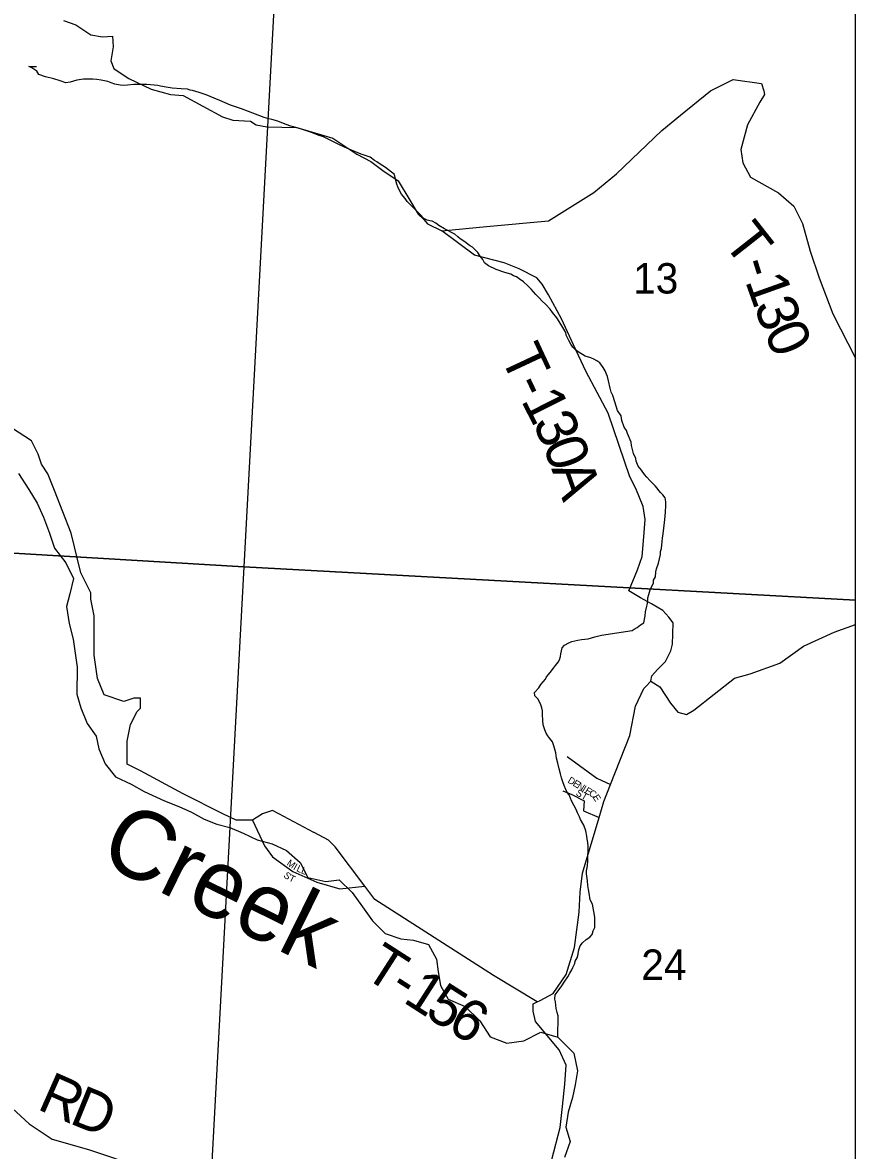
# Model space of a CAD drawing. Extents: x 1949938.81 to 1949945.61, y 152207.65 to 152214.09.
# Drawn here: x 1949944.46 to 1949945.607, y 152211.223 to 152212.776 of the extents above; entities that cross this region are included whole.
import ezdxf

# ---------------------------------------------------------------- set-up
doc = ezdxf.new("R2010")
doc.units = 0
for name, color, linetype in [('GM_X_County', 7, 'Continuous'), ('GM_X_County_Road', 7, 'Continuous'), ('GM_X_County_Road_Text', 7, 'Continuous'), ('GM_X_Minor_River', 7, 'Continuous'), ('GM_X_Minor_River_Text', 7, 'Continuous'), ('GM_X_Section', 7, 'Continuous'), ('GM_X_Section_Text', 7, 'Continuous'), ('GM_X_Township', 7, 'Continuous'), ('GM_X_Township_Road', 7, 'Continuous'), ('GM_X_Township_Road_Text', 7, 'Continuous'), ('GM_X_Township_ROW', 7, 'Continuous'), ('GM_X_Township_Subdivision', 7, 'Continuous'), ('GM_X_Township_Subdivision_Text', 7, 'Continuous')]:
    doc.layers.add(name, color=color, linetype=linetype)

msp = doc.modelspace()

# ---------------------------------------------------------------- linework, layer by layer
at = {"layer": 'GM_X_County'}
msp.add_lwpolyline([(1949945.6069, 152208.8266), (1949945.6069, 152214.0874), (1949938.8069, 152214.0874), (1949938.8069, 152213.1813)], dxfattribs=at)
at = {"layer": 'GM_X_County_Road'}
for points in [[(1949945.3182, 152211.8618), (1949945.3182, 152211.8618), (1949945.3252, 152211.8688), (1949945.3375, 152211.861), (1949945.352, 152211.8389), (1949945.3624, 152211.8264), (1949945.3742, 152211.823), (1949945.3845, 152211.8292), (1949945.4404, 152211.8733), (1949945.462, 152211.8791), (1949945.5029, 152211.8936), (1949945.5355, 152211.9172), (1949945.5775, 152211.9366), (1949945.6069, 152211.9469)], [(1949943.7253, 152211.8724), (1949943.7713, 152211.8759), (1949943.7925, 152211.8688), (1949943.8248, 152211.8553), (1949943.8598, 152211.8405), (1949943.959, 152211.7945), (1949944.0299, 152211.7626), (1949944.0547, 152211.7307), (1949944.0901, 152211.674), (1949944.1184, 152211.6421), (1949944.2424, 152211.5252), (1949944.2637, 152211.5004), (1949944.3132, 152211.426), (1949944.3876, 152211.3339), (1949944.4691, 152211.2594), (1949944.501, 152211.2382), (1949944.5506, 152211.224), (1949944.6249, 152211.1992)], [(1949945.189, 152211.2101), (1949945.2003, 152211.2539), (1949945.2036, 152211.2831), (1949945.2068, 152211.314), (1949945.2084, 152211.3399), (1949945.1987, 152211.361), (1949945.1662, 152211.4), (1949945.163, 152211.4146), (1949945.163, 152211.4243), (1949945.1686, 152211.4271), (1949945.1727, 152211.4292), (1949945.1906, 152211.4389), (1949945.2084, 152211.4649), (1949945.2198, 152211.5022), (1949945.2263, 152211.5508), (1949945.2279, 152211.5784), (1949945.2311, 152211.6044), (1949945.2538, 152211.6811), (1949945.2603, 152211.7033), (1949945.2694, 152211.7265), (1949945.296, 152211.7942), (1949945.3041, 152211.8347), (1949945.3155, 152211.859), (1949945.3182, 152211.8618)]]:
    msp.add_lwpolyline(points, dxfattribs=at)
at = {"layer": 'GM_X_Minor_River'}
for points in [[(1949945.0903, 152212.4545), (1949945.087, 152212.4595), (1949945.0833, 152212.463), (1949945.0795, 152212.4668), (1949945.0754, 152212.4692), (1949945.0691, 152212.4742), (1949945.0627, 152212.4785), (1949945.0593, 152212.4812), (1949945.0552, 152212.4847), (1949945.041, 152212.4922), (1949945.0331, 152212.4965), (1949945.029, 152212.5), (1949945.0241, 152212.5027), (1949945.0207, 152212.5031), (1949945.0173, 152212.504), (1949945.0124, 152212.5063), (1949945.0069, 152212.5121), (1949945.0024, 152212.5171), (1949944.9976, 152212.5218), (1949944.9942, 152212.5252), (1949944.9898, 152212.5299), (1949944.9868, 152212.5337), (1949944.9816, 152212.5399), (1949944.9794, 152212.5441), (1949944.9768, 152212.5498), (1949944.9754, 152212.5537), (1949944.974, 152212.5586), (1949944.9722, 152212.567), (1949944.9599, 152212.5767), (1949944.9524, 152212.5814), (1949944.9479, 152212.5845), (1949944.9445, 152212.5861), (1949944.9386, 152212.5907), (1949944.9261, 152212.5948), (1949944.913, 152212.6003), (1949944.9032, 152212.6046), (1949944.8964, 152212.6078), (1949944.8893, 152212.6117), (1949944.881, 152212.6156), (1949944.8743, 152212.6188), (1949944.8683, 152212.6208), (1949944.8581, 152212.6248), (1949944.8453, 152212.6288), (1949944.8329, 152212.6324), (1949944.8295, 152212.6336), (1949944.8231, 152212.636), (1949944.8193, 152212.6372), (1949944.8114, 152212.6404), (1949944.8031, 152212.6428), (1949944.799, 152212.6436), (1949944.7929, 152212.6456), (1949944.7869, 152212.648), (1949944.7711, 152212.6536), (1949944.7617, 152212.6572), (1949944.7546, 152212.6596), (1949944.7463, 152212.6624), (1949944.7388, 152212.6659), (1949944.7316, 152212.6691), (1949944.7237, 152212.6722), (1949944.7128, 152212.6766), (1949944.7034, 152212.6798), (1949944.694, 152212.6826), (1949944.6906, 152212.6831), (1949944.6872, 152212.6843), (1949944.6785, 152212.6852), (1949944.666, 152212.6861), (1949944.6577, 152212.6874), (1949944.6498, 152212.6887), (1949944.6464, 152212.6895), (1949944.6312, 152212.6909), (1949944.6134, 152212.6908), (1949944.6047, 152212.6898), (1949944.599, 152212.6895), (1949944.5945, 152212.69), (1949944.5873, 152212.6913), (1949944.5821, 152212.6933), (1949944.5775, 152212.6952), (1949944.5681, 152212.6969), (1949944.5624, 152212.6978), (1949944.5568, 152212.6982), (1949944.5507, 152212.6983), (1949944.5439, 152212.6981), (1949944.5348, 152212.6967), (1949944.5256, 152212.6942), (1949944.5196, 152212.6932), (1949944.512, 152212.696), (1949944.503, 152212.6988), (1949944.4917, 152212.7016), (1949944.4826, 152212.7048), (1949944.4797, 152212.7094), (1949944.4726, 152212.7141), (1949944.4688, 152212.7157), (1949944.4794, 152212.7159)], [(1949945.2993, 152211.9387), (1949945.3024, 152211.9405), (1949945.3063, 152211.9427), (1949945.3109, 152211.9464), (1949945.3155, 152211.9494), (1949945.3172, 152211.9589), (1949945.3176, 152211.9646), (1949945.3197, 152211.9725), (1949945.3205, 152211.9759), (1949945.321, 152211.9839), (1949945.3222, 152211.9884), (1949945.3242, 152211.9948), (1949945.3286, 152212.0046), (1949945.329, 152212.008), (1949945.3314, 152212.0126), (1949945.3322, 152212.0194), (1949945.3331, 152212.0239), (1949945.3355, 152212.0315), (1949945.3384, 152212.0436), (1949945.3384, 152212.0478), (1949945.3396, 152212.0519), (1949945.3406, 152212.0614), (1949945.341, 152212.0659), (1949945.3423, 152212.072), (1949945.3432, 152212.0796), (1949945.344, 152212.0875), (1949945.345, 152212.0963), (1949945.3451, 152212.1023), (1949945.3456, 152212.1103), (1949945.3457, 152212.116), (1949945.3447, 152212.1217), (1949945.3417, 152212.1255), (1949945.3383, 152212.129), (1949945.3317, 152212.1375), (1949945.3283, 152212.1406), (1949945.3239, 152212.1456), (1949945.3194, 152212.1502), (1949945.3164, 152212.1537), (1949945.3124, 152212.1595), (1949945.3079, 152212.1652), (1949945.305, 152212.1721), (1949945.3043, 152212.1759), (1949945.3014, 152212.1824), (1949945.2986, 152212.1935), (1949945.2979, 152212.1981), (1949945.2928, 152212.2103), (1949945.2917, 152212.2145), (1949945.2884, 152212.2187), (1949945.2852, 152212.2283), (1949945.2841, 152212.2344), (1949945.2793, 152212.2417), (1949945.2754, 152212.2539), (1949945.2729, 152212.2623), (1949945.2707, 152212.2673), (1949945.2693, 152212.2726), (1949945.2668, 152212.2829), (1949945.2654, 152212.2886), (1949945.2639, 152212.2921), (1949945.2621, 152212.2963), (1949945.2596, 152212.3009), (1949945.2551, 152212.3074), (1949945.251, 152212.3101), (1949945.2465, 152212.3125), (1949945.2424, 152212.3145), (1949945.2348, 152212.3169), (1949945.2311, 152212.3188), (1949945.2266, 152212.3219), (1949945.2214, 152212.3254), (1949945.2176, 152212.3289), (1949945.2151, 152212.3331), (1949945.2121, 152212.3385), (1949945.2085, 152212.3458), (1949945.2081, 152212.3492), (1949945.2011, 152212.3607), (1949945.1956, 152212.3695), (1949945.1897, 152212.3769), (1949945.1864, 152212.3815), (1949945.1804, 152212.388), (1949945.1752, 152212.3931), (1949945.1715, 152212.3969), (1949945.1666, 152212.4016), (1949945.1603, 152212.4089), (1949945.1559, 152212.4135), (1949945.1499, 152212.4189), (1949945.1439, 152212.4232), (1949945.1402, 152212.4259), (1949945.136, 152212.4275), (1949945.1323, 152212.4295), (1949945.124, 152212.4319), (1949945.112, 152212.4363), (1949945.1018, 152212.441), (1949945.0962, 152212.4453), (1949945.0936, 152212.4499), (1949945.0903, 152212.4545)], [(1949944.4544, 152212.1551), (1949944.4687, 152212.133), (1949944.48, 152212.114), (1949944.489, 152212.095), (1949944.4972, 152212.0729), (1949944.5039, 152212.0524), (1949944.5198, 152212.0318), (1949944.5303, 152212.0105), (1949944.5249, 152211.9893), (1949944.5203, 152211.9719), (1949944.524, 152211.9483), (1949944.5299, 152211.927), (1949944.5351, 152211.8883), (1949944.5349, 152211.8511), (1949944.5401, 152211.8321), (1949944.5491, 152211.8108), (1949944.5612, 152211.7933), (1949944.5649, 152211.7758), (1949944.5739, 152211.7552), (1949944.5882, 152211.737), (1949944.6094, 152211.727), (1949944.6275, 152211.7171), (1949944.6555, 152211.7041), (1949944.6751, 152211.6964), (1949944.6925, 152211.6887), (1949944.7099, 152211.6788), (1949944.7273, 152211.6719), (1949944.7454, 152211.6673), (1949944.7636, 152211.6596), (1949944.7832, 152211.6504), (1949944.8037, 152211.645), (1949944.8233, 152211.6359), (1949944.8422, 152211.6191), (1949944.8527, 152211.5985), (1949944.8777, 152211.5931), (1949944.8959, 152211.5953), (1949944.914, 152211.5778), (1949944.9283, 152211.558), (1949944.9418, 152211.539), (1949944.9592, 152211.5214), (1949944.9811, 152211.5138), (1949944.9985, 152211.5122), (1949945.0189, 152211.506), (1949945.0302, 152211.4862), (1949945.0324, 152211.4687), (1949945.0354, 152211.4497), (1949945.0459, 152211.4307), (1949945.0693, 152211.4208), (1949945.0897, 152211.4009), (1949945.104, 152211.3788), (1949945.1267, 152211.3704), (1949945.1502, 152211.3734), (1949945.1737, 152211.3854), (1949945.1971, 152211.3785), (1949945.219, 152211.3564), (1949945.2242, 152211.3321), (1949945.2211, 152211.3131), (1949945.2173, 152211.2956), (1949945.2111, 152211.2751), (1949945.208, 152211.2546), (1949945.214, 152211.2348), (1949945.2063, 152211.2128)], [(1949945.1971, 152211.3785), (1949945.1976, 152211.4078), (1949945.1962, 152211.4124), (1949945.1948, 152211.4181), (1949945.1938, 152211.4272), (1949945.1931, 152211.431), (1949945.1936, 152211.4371), (1949945.199, 152211.4442), (1949945.2025, 152211.4495), (1949945.2056, 152211.4544), (1949945.2107, 152211.4615), (1949945.2138, 152211.4668), (1949945.2162, 152211.4713), (1949945.2177, 152211.4747), (1949945.2205, 152211.48), (1949945.2209, 152211.4834), (1949945.2237, 152211.4879), (1949945.2249, 152211.4928), (1949945.2257, 152211.497), (1949945.2265, 152211.5004), (1949945.2277, 152211.5042), (1949945.2312, 152211.5087), (1949945.2362, 152211.5131), (1949945.2412, 152211.5165), (1949945.2443, 152211.5198), (1949945.2459, 152211.5251), (1949945.2479, 152211.5297), (1949945.248, 152211.5392), (1949945.2478, 152211.5441), (1949945.2467, 152211.5517), (1949945.245, 152211.562), (1949945.2417, 152211.5678), (1949945.24, 152211.5769), (1949945.2393, 152211.5819), (1949945.2383, 152211.5876), (1949945.238, 152211.594), (1949945.2367, 152211.6036), (1949945.2367, 152211.6077), (1949945.238, 152211.6146), (1949945.2385, 152211.621), (1949945.2389, 152211.6419), (1949945.2386, 152211.6468), (1949945.2375, 152211.6514), (1949945.2372, 152211.6556), (1949945.2358, 152211.6628), (1949945.2329, 152211.6705), (1949945.2285, 152211.6785), (1949945.2271, 152211.682), (1949945.2241, 152211.6877), (1949945.2223, 152211.6923), (1949945.2157, 152211.7042), (1949945.2143, 152211.7077), (1949945.2125, 152211.7122), (1949945.2099, 152211.7157), (1949945.208, 152211.7199), (1949945.2059, 152211.7253), (1949945.2041, 152211.7302), (1949945.2023, 152211.736), (1949945.2008, 152211.7413), (1949945.1987, 152211.7482), (1949945.1969, 152211.7558), (1949945.1952, 152211.7631), (1949945.1942, 152211.7703), (1949945.1917, 152211.7798), (1949945.1899, 152211.7852), (1949945.1862, 152211.7898), (1949945.1832, 152211.7936), (1949945.181, 152211.7975), (1949945.1792, 152211.8021), (1949945.177, 152211.8089), (1949945.1764, 152211.8147), (1949945.1761, 152211.823), (1949945.1759, 152211.828), (1949945.1752, 152211.8321), (1949945.173, 152211.8379), (1949945.1697, 152211.8448), (1949945.1652, 152211.849), (1949945.1649, 152211.8536), (1949945.1707, 152211.86), (1949945.1738, 152211.8645), (1949945.18, 152211.8716), (1949945.1816, 152211.875), (1949945.1863, 152211.881), (1949945.1913, 152211.8869), (1949945.194, 152211.8907), (1949945.1975, 152211.8952), (1949945.1994, 152211.8986), (1949945.2007, 152211.9031), (1949945.2011, 152211.9065), (1949945.2019, 152211.9107), (1949945.2031, 152211.9149), (1949945.2062, 152211.9186), (1949945.212, 152211.9219), (1949945.2165, 152211.9237), (1949945.2245, 152211.9255), (1949945.2295, 152211.9262), (1949945.239, 152211.9275), (1949945.2481, 152211.93), (1949945.2534, 152211.9315), (1949945.2572, 152211.9325), (1949945.2993, 152211.9387)]]:
    msp.add_lwpolyline(points, dxfattribs=at)
at = {"layer": 'GM_X_Section'}
for p, q in [((1949945.6069, 152211.9807), (1949945.6069, 152213.0111)), ((1949945.6069, 152210.9665), (1949945.6069, 152211.9807))]:
    msp.add_line(p, q, dxfattribs=at)
for points in [[(1949944.8197, 152213.0519), (1949944.7648, 152212.0263), (1949943.6665, 152212.0918), (1949943.7308, 152213.1166)], [(1949943.6665, 152212.0918), (1949944.7648, 152212.0263), (1949944.7104, 152211.0185), (1949943.6063, 152211.0859)]]:
    msp.add_lwpolyline(points, close=True, dxfattribs=at)
for points in [[(1949945.6069, 152213.0111), (1949944.8197, 152213.0519), (1949944.7648, 152212.0263), (1949945.6069, 152211.9807)], [(1949945.6069, 152211.9807), (1949944.7648, 152212.0263), (1949944.7104, 152211.0185), (1949945.6069, 152210.9665)]]:
    msp.add_lwpolyline(points, dxfattribs=at)
at = {"layer": 'GM_X_Township'}
msp.add_lwpolyline([(1949945.6069, 152208.8266), (1949945.6069, 152214.0874), (1949942.6839, 152214.0874)], dxfattribs=at)
at = {"layer": 'GM_X_Township_Road'}
for points in [[(1949945.366, 152212.6486), (1949945.4075, 152212.6821), (1949945.4387, 152212.6977), (1949945.4776, 152212.6925), (1949945.4809, 152212.6824), (1949945.4817, 152212.677), (1949945.4753, 152212.6664), (1949945.4583, 152212.6356), (1949945.4489, 152212.6015), (1949945.4516, 152212.5829), (1949945.4623, 152212.5632), (1949945.501, 152212.5416), (1949945.5219, 152212.5235), (1949945.5341, 152212.4996), (1949945.5444, 152212.4613), (1949945.557, 152212.4245), (1949945.5757, 152212.3752), (1949945.6069, 152212.314)], [(1949945.2188, 152212.3322), (1949945.202, 152212.368), (1949945.1844, 152212.4012), (1949945.1757, 152212.416), (1949945.1681, 152212.4244), (1949945.1438, 152212.4372), (1949945.1234, 152212.4453), (1949945.0821, 152212.4558), (1949945.0374, 152212.4892)], [(1949945.3252, 152211.8688), (1949945.3264, 152211.8765), (1949945.3341, 152211.8852), (1949945.3453, 152211.8959), (1949945.3529, 152211.9107), (1949945.355, 152211.9201), (1949945.3552, 152211.9339), (1949945.3557, 152211.9492), (1949945.3499, 152211.9571), (1949945.3415, 152211.9663), (1949945.3262, 152211.9755), (1949945.3111, 152211.9839), (1949945.2948, 152211.9936), (1949945.307, 152212.0222), (1949945.3132, 152212.0405), (1949945.3157, 152212.0676), (1949945.3172, 152212.0915), (1949945.3147, 152212.1094), (1949945.3045, 152212.1344), (1949945.2963, 152212.1507), (1949945.2662, 152212.238), (1949945.2362, 152212.2953), (1949945.2188, 152212.3322)], [(1949944.8613, 152211.6607), (1949944.8131, 152211.6864), (1949944.804, 152211.691), (1949944.7904, 152211.6864), (1949944.7768, 152211.6773), (1949944.7541, 152211.6773), (1949944.7359, 152211.6864), (1949944.6813, 152211.7137), (1949944.6223, 152211.7455), (1949944.6041, 152211.7546), (1949944.6041, 152211.7864), (1949944.6086, 152211.8091), (1949944.6177, 152211.8273), (1949944.6223, 152211.8318), (1949944.6223, 152211.8455), (1949944.6132, 152211.8455), (1949944.5995, 152211.8409), (1949944.5723, 152211.85), (1949944.5632, 152211.8728), (1949944.5586, 152211.9046), (1949944.5586, 152211.9591), (1949944.5541, 152211.9818), (1949944.5541, 152211.9909), (1949944.5404, 152212.0182), (1949944.5268, 152212.0727), (1949944.5041, 152212.1318), (1949944.495, 152212.1545), (1949944.4859, 152212.1681), (1949944.4814, 152212.1818), (1949944.4723, 152212.1999), (1949944.445, 152212.2181)], [(1949945.1686, 152211.4271), (1949945.1086, 152211.4636), (1949944.9449, 152211.5682), (1949944.9313, 152211.5864), (1949944.8904, 152211.6409), (1949944.8813, 152211.65), (1949944.8615, 152211.6606), (1949944.8613, 152211.6607)]]:
    msp.add_lwpolyline(points, dxfattribs=at)
at = {"layer": 'GM_X_Township_ROW'}
msp.add_lwpolyline([(1949944.5162, 152212.779), (1949944.5333, 152212.7731), (1949944.5542, 152212.7593), (1949944.5703, 152212.7568), (1949944.584, 152212.7573), (1949944.5848, 152212.7428), (1949944.5815, 152212.7236), (1949944.5858, 152212.7132), (1949944.5973, 152212.705), (1949944.6065, 152212.6991), (1949944.6371, 152212.6846), (1949944.6636, 152212.6772), (1949944.6814, 152212.6757), (1949944.7355, 152212.6463), (1949944.7495, 152212.642), (1949944.774, 152212.6405), (1949944.7817, 152212.6354), (1949944.7965, 152212.6328), (1949944.8378, 152212.6318), (1949944.8873, 152212.617), (1949944.9204, 152212.5951), (1949944.9398, 152212.5849), (1949944.9561, 152212.5726), (1949944.977, 152212.5583), (1949944.9934, 152212.5318), (1949945.0046, 152212.5124), (1949945.0125, 152212.5048), (1949945.0178, 152212.4992), (1949945.0374, 152212.4892), (1949945.0987, 152212.4954), (1949945.1844, 152212.5031), (1949945.2466, 152212.542), (1949945.2778, 152212.568), (1949945.3401, 152212.6276), (1949945.366, 152212.6486)], dxfattribs=at)
at = {"layer": 'GM_X_Township_Subdivision'}
for points in [[(1949945.2099, 152211.7652), (1949945.2506, 152211.7353), (1949945.2694, 152211.7265)], [(1949945.2039, 152211.7178), (1949945.2162, 152211.7127), (1949945.2335, 152211.7042), (1949945.2322, 152211.6903), (1949945.2538, 152211.6811)], [(1949944.7768, 152211.6773), (1949944.7932, 152211.642), (1949944.8043, 152211.6272), (1949944.8321, 152211.6069), (1949944.8653, 152211.5921), (1949944.8968, 152211.5828), (1949944.9313, 152211.5864)]]:
    msp.add_lwpolyline(points, dxfattribs=at)

# ---------------------------------------------------------------- texts
at = {"layer": 'GM_X_County_Road_Text'}
for s, rotation, p in [('R', 336.144, (1949944.4785, 152211.2801)), ('D', 337.8426, (1949944.5229, 152211.2605))]:
    msp.add_text(s, height=0.0568, rotation=rotation, dxfattribs=at).set_placement(p)
at = {"layer": 'GM_X_Minor_River_Text'}
msp.add_text('Creek', height=0.0947, rotation=333.7756, dxfattribs=at).set_placement((1949944.5619, 152211.6215))
at = {"layer": 'GM_X_Section_Text'}
for s, p in [('13', (1949945.3007, 152212.403)), ('24', (1949945.312, 152211.4575))]:
    msp.add_text(s, height=0.04186, rotation=0, dxfattribs=at).set_placement(p)
at = {"layer": 'GM_X_Township_Road_Text'}
for s, rotation, p in [('T', 308.206, (1949945.4231, 152212.4734)), ('-', 287.3509, (1949945.4469, 152212.4449)), ('1', 289.5887, (1949945.4546, 152212.4203)), ('3', 290.0178, (1949945.4665, 152212.3869)), ('0', 293.9829, (1949945.4801, 152212.35)), ('T', 295.0707, (1949945.1171, 152212.3171)), ('-', 295.5066, (1949945.1353, 152212.2782)), ('1', 296.7734, (1949945.1459, 152212.2559)), ('3', 295.2817, (1949945.1615, 152212.225)), ('0', 289.9467, (1949945.1759, 152212.1947)), ('A', 289.6227, (1949945.1878, 152212.1619)), ('T', 327.265, (1949944.927, 152211.4633)), ('-', 327.2813, (1949944.9627, 152211.4404)), ('1', 327.3352, (1949944.9824, 152211.4277)), ('5', 327.5691, (1949945.0121, 152211.4087)), ('6', 328.6213, (1949945.0426, 152211.3893))]:
    msp.add_text(s, height=0.0568, rotation=rotation, dxfattribs=at).set_placement(p)
at = {"layer": 'GM_X_Township_Subdivision_Text'}
for s, rotation, p in [('D', 328.7313, (1949945.2098, 152211.7299)), ('E', 328.7158, (1949945.2169, 152211.7256)), ('ST', 330.2553, (1949945.221, 152211.7125)), ('N', 328.7349, (1949945.2226, 152211.7221)), ('I', 328.7223, (1949945.2297, 152211.7178)), ('E', 328.7375, (1949945.2333, 152211.7156)), ('C', 328.7181, (1949945.239, 152211.7122)), ('E', 303.154, (1949945.2446, 152211.7091)), ('M', 325.0597, (1949944.8229, 152211.6163)), ('I', 330.3156, (1949944.8319, 152211.6101)), ('L', 335.5714, (1949944.8364, 152211.6076)), ('L', 338.1993, (1949944.8428, 152211.6047)), ('S', 320.5311, (1949944.8185, 152211.6)), ('T', 334.6228, (1949944.8258, 152211.5944))]:
    msp.add_text(s, height=0.00947, rotation=rotation, dxfattribs=at).set_placement(p)

doc.saveas('drawing.dxf')
